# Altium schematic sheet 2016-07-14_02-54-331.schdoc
size 575 x 193 mm; SheetNumber: 1; SheetTotal: 1
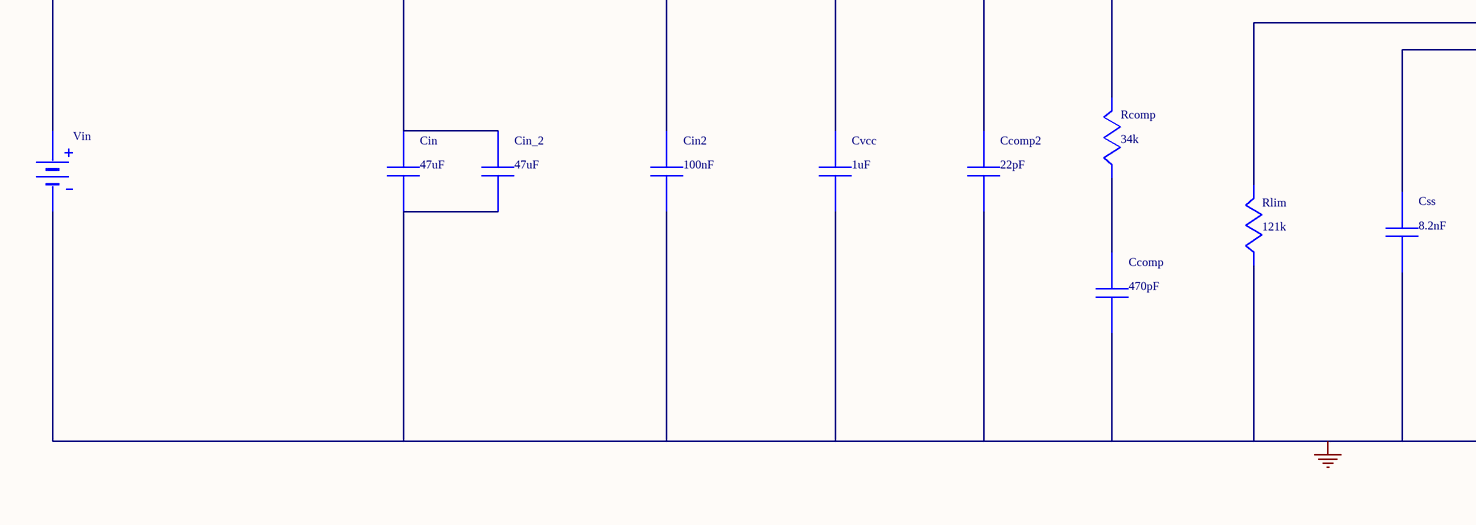
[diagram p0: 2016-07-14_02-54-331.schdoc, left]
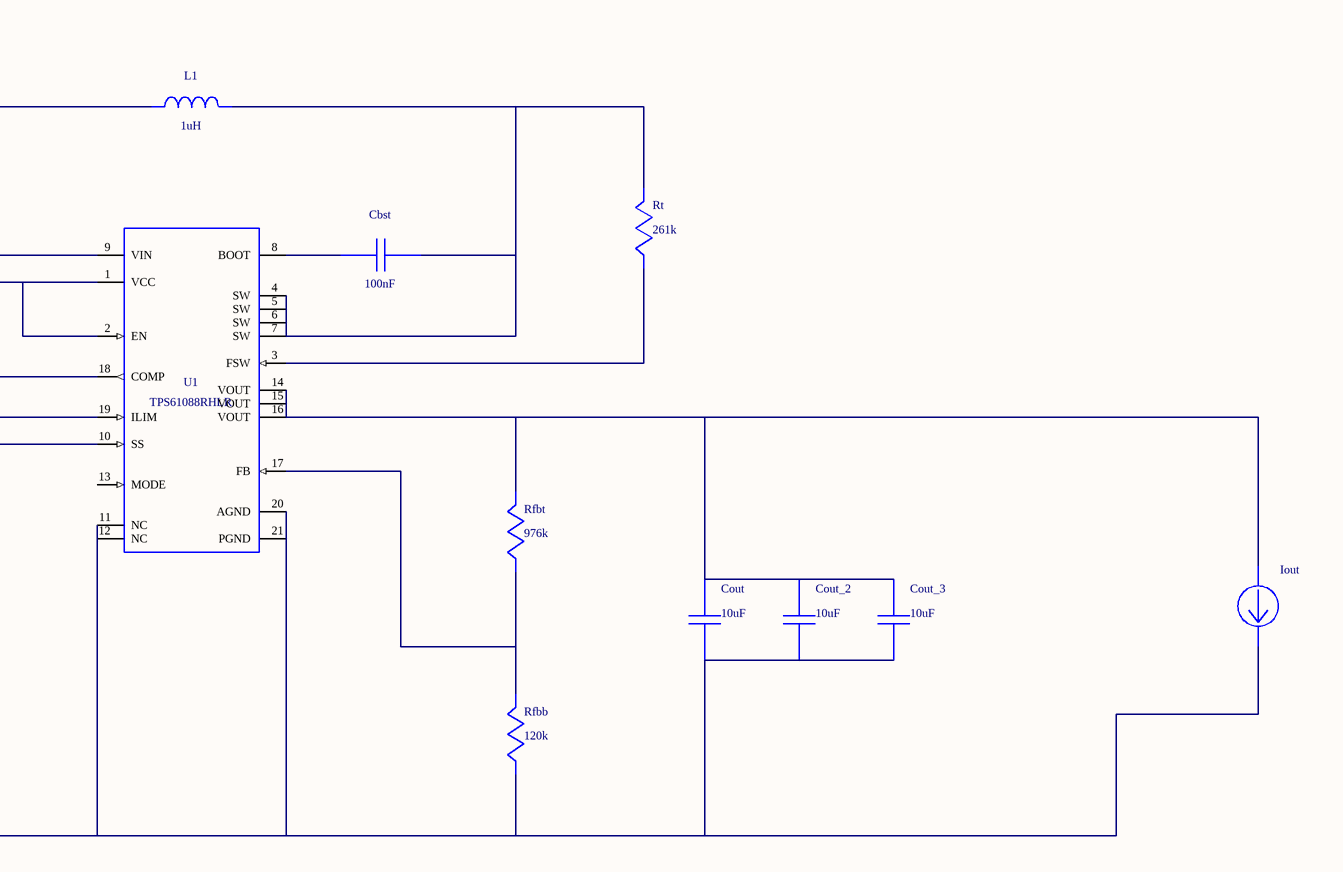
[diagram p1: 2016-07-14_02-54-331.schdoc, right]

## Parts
Cbst  value 100nF  (hidden comment: 08053C104KAT2A)
Ccomp  value 470pF  (hidden comment: GRM033R71C471KA01D)
Ccomp2  value 22pF  (hidden comment: GRM0225C1C220JD05L)
Cin  value 47uF  (hidden comment: GRM32ER61C476ME15L)
Cin2  value 100nF  (hidden comment: GRM155R61C104KA88D)
Cin_2  value 47uF  (hidden comment: GRM32ER61C476ME15L)
Cout  value 10uF  (hidden comment: GRM31CR61E106KA12L)
Cout_2  value 10uF  (hidden comment: GRM31CR61E106KA12L)
Cout_3  value 10uF  (hidden comment: GRM31CR61E106KA12L)
Css  value 8.2nF  (hidden comment: GRM155R71C822KA01D)
Cvcc  value 1uF  (hidden comment: GRM188R61A105KA61D)
Iout  WB_CURRENT_LOAD  (value not drawn)
L1  value 1uH  (hidden comment: VLP8040T-1R0N)
Rcomp  value 34k  (hidden comment: CRCW040234K0FKED)
Rfbb  value 120k  (hidden comment: RC0603FR-07120KL)
Rfbt  value 976k  (hidden comment: CRCW0402976KFKED)
Rlim  value 121k  (hidden comment: CRCW0402121KFKED)
Rt  value 261k  (hidden comment: CRCW0402261KFKED)
U1  TPS61088RHLR
Vin  WB_BATTERY  (value not drawn)

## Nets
0: Ccomp.2 Ccomp2.2 Cin.2 Cin2.2 Cin_2.2 Cout.2 Cout_2.2 Cout_3.2 Css.2 Cvcc.2 Iout.2(-) Rfbb.2 Rlim.2 U1.11(NC) U1.12(NC) U1.20(AGND) U1.21(PGND) Vin.2(-)
NetCbst_1: Cbst.1 U1.8(BOOT)
NetCbst_2: Cbst.2 L1.2 Rt.1 U1.4(SW) U1.5(SW) U1.6(SW) U1.7(SW)
NetCcomp2_1: Ccomp2.1 Rcomp.1 U1.18(COMP)
NetCcomp_1: Ccomp.1 Rcomp.2
NetCin_1: Cin.1 Cin2.1 Cin_2.1 L1.1 U1.9(VIN) Vin.1(+)
NetCout_1: Cout.1 Cout_2.1 Cout_3.1 Iout.1(+) Rfbt.1 U1.14(VOUT) U1.15(VOUT) U1.16(VOUT)
NetCss_1: Css.1 U1.10(SS)
NetCvcc_1: Cvcc.1 U1.1(VCC) U1.2(EN)
NetRfbb_1: Rfbb.1 Rfbt.2 U1.17(FB)
NetRlim_1: Rlim.1 U1.19(ILIM)
NetRt_2: Rt.2 U1.3(FSW)

Not connected (* = marked no-connect by the designer): U1 13(MODE)

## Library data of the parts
Cbst = 08053C104KAT2A: Manufacturer Name: AVX
Ccomp = GRM033R71C471KA01D: GRM033R71C471KA0; Manufacturer Name: MuRata
Ccomp2 = GRM0225C1C220JD05L: GRM0225C1C220JD0; Manufacturer Name: MuRata
Cin Cin_2 = GRM32ER61C476ME15L: GRM32ER61C476ME1; Manufacturer Name: MuRata
Cin2 = GRM155R61C104KA88D: GRM155R61C104KA8; Manufacturer Name: MuRata
Cout Cout_2 Cout_3 = GRM31CR61E106KA12L: GRM31CR61E106KA1; Manufacturer Name: MuRata
Css = GRM155R71C822KA01D: GRM155R71C822KA0; Manufacturer Name: MuRata
Cvcc = GRM188R61A105KA61D: GRM188R61A105KA6; Manufacturer Name: MuRata
L1 = VLP8040T-1R0N: Unknown; Manufacturer Name: TDK
Rcomp = CRCW040234K0FKED: Manufacturer Name: Vishay-Dale
Rfbb = RC0603FR-07120KL: Manufacturer Name: Yageo America
Rfbt = CRCW0402976KFKED: Manufacturer Name: Vishay-Dale
Rlim = CRCW0402121KFKED: Manufacturer Name: Vishay-Dale
Rt = CRCW0402261KFKED: Manufacturer Name: Vishay-Dale
U1 = TPS61088RHLR: Manufacturer Name: Texas Instruments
